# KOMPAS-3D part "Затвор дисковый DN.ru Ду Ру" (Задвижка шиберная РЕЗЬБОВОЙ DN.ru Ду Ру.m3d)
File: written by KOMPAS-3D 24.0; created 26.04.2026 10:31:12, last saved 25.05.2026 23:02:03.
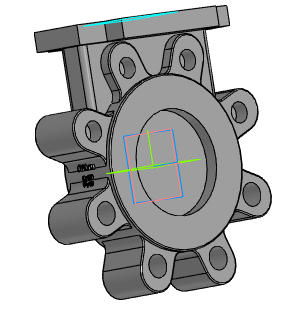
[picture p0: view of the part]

Document properties: Автор: R2D2; Полное имя файла: E:\Работа\Зайцев\GVKR1331M-1W-Fb-2P Задвижка шиберная с выдвижным штоком DN.ru Ду50-300 Ру16-10-6 с пневмоприводом\исходные материалы\DN80\Задвижка шиберная РЕЗЬБОВОЙ DN.ru Ду Ру.m3d

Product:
- Part/product: Затвор дисковый DN.ru Ду Ру
    Масса: 18.2
    Раздел спецификации: Прочие изделия
    Примечание: D050-23732

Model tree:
1. Смещенная плоскость:2
2. Диск
3. Корпус
4. Элемент выдавливания:3
     Расстояние 1 = 30
5. Элемент вращения:1
     Угол 1 = 360
6. Корпус штока
7. Элемент выдавливания:6  (with: Грань.Элемент вращения:1)
     Расстояние 1 = 110
8. Ушко  (with: Ребро.Элемент вращения:1)
9. Элемент выдавливания:5
10. Скругление:7  (with: Ребро.Элемент выдавливания:5)
     Радиус = 1
11. Эскиз:1  (with: Ребро.Элемент выдавливания:5)
12. Элемент выдавливания:12
     Расстояние 1 = 25.5
13. Элемент выдавливания:13
14. Массив по концентрической сетке:1  (with: Элемент выдавливания:13, Элемент выдавливания:12, Элемент выдавливания:5, Скругление:7)  (8 pattern instances)
     Шаг 2 = 360
15. Эскиз:2  (labels: Ребро.Элемент выдавливания:5.Экземпляр ( 1, 4 ); Ребро.Элемент выдавливания:5.Экземпляр ( 1, 5 ); Ребро.Элемент выдавливания:5.Экземпляр ( 1, 6 ); Ребро.Элемент выдавливания:5.Экземпляр ( 1, 3 ))
16. Элемент выдавливания:14
17. площадка  (with: Грань.Элемент выдавливания:6, Грань.Элемент выдавливания:5)
18. Элемент выдавливания:15
     Расстояние 2 = 15
19. Скругление:10  (with: Ребро.Элемент выдавливания:6)
     Радиус = 5
20. Эскиз:4  (labels: Задвижка шиберная с выдвижным штоком DN.ru Ду50 Ру16; Затвор дисковый DN.ru Ду200 Ру16)
21. Элемент выдавливания:16  (with: Грань.Элемент вращения:1)
     Расстояние 1 = 67; Смещение 1 = 1
22. Эскиз:5  (labels: Задвижка шиберная DN.ru Ду50 Ру10; Затвор дисковый DN.ru Ду200 Ру16)
23. Элемент выдавливания:17  (with: Грань.Элемент вращения:1)
     Расстояние 1 = 67.9966; Смещение 1 = 2
24. Скругление:8  (with: Ребро.Элемент вращения:1)
     Радиус = 1

Expressions: 360/n; c-8-2*t; v1301/2; dd/2; d/2+30
Referenced files in E:\Работа\Зайцев\GVKR1331E-1W-Fb-2P Задвижка шиберная DN.ru Ду50-300 Ру16-10-6\исходные материалы\DN50\: GVKR1331E-1W-Fb-2P Задвижка шиберная с выдвижным штоком DN.ru Ду50 Ру16.a3d, GVKR1331E-1W-Fb-2P Задвижка шиберная DN.ru Ду50 Ру16.a3d
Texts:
  Угловой размер с обрывом
  GOST 26.020 Pr3
  var3D
  ширина затвора по металлу
  площадка под крепеж
  DN+10
  dk-4
  dk+20
  Плоскость ZY.Начало координат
